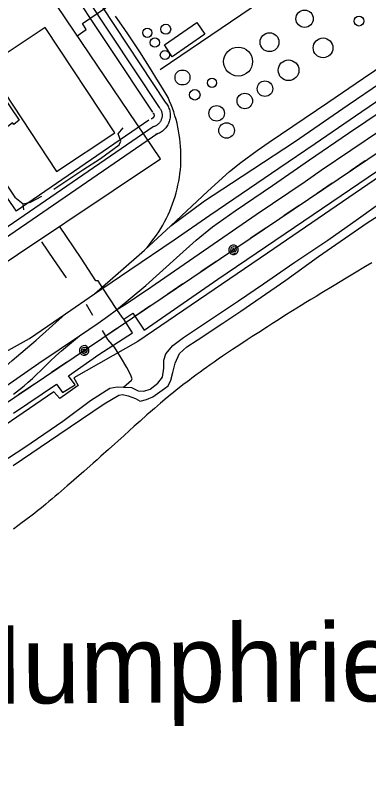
# Model space of a CAD drawing. Extents: x 3355724 to 3393621, y 594744 to 620174.
# Drawn here: x 3387262 to 3387918, y 615262 to 616675 of the extents above; entities that cross this region are included whole.
import ezdxf

# ---------------------------------------------------------------- set-up
doc = ezdxf.new("R2010")
doc.units = 0
for name, color, linetype in [('V-BLDG-OTLN', 7, 'Continuous'), ('V-DOMW-TANK', 7, 'Continuous'), ('V-RAIL-TRAK', 7, 'Continuous'), ('V-ROAD-CNTR', 7, 'Continuous'), ('V-SITE-OTLN', 7, 'Continuous'), ('V-TOPO-GNAM-IDEN', 7, 'Continuous'), ('V-TOPO-SHOR', 7, 'Continuous'), ('V-UTIL-LINE', 7, 'Continuous')]:
    doc.layers.add(name, color=color, linetype=linetype)

msp = doc.modelspace()

# ---------------------------------------------------------------- linework, layer by layer
at = {"layer": 'V-BLDG-OTLN'}
for points in [[(3387553.3, 616598.3), (3387539.4, 616620.3), (3387599.5, 616661.8), (3387614.3, 616640.3)], [(3387201.5, 616455.7), (3387181.3, 616482), (3387221.2, 616512.5), (3387206, 616532.9), (3387166.4, 616504.6), (3387146.8, 616534.8), (3387204.5, 616575.5), (3387269.8, 616480.5), (3387259.4, 616472.8), (3387257.3, 616475.6), (3387245.2, 616466.3), (3387238, 616475.6), (3387230.3, 616469.7), (3387226.4, 616474.8)]]:
    msp.add_lwpolyline(points, close=True, dxfattribs=at)
at = {"layer": 'V-DOMW-TANK'}
for centre, radius in [((3387799.3, 616668.6), 16.1), ((3387900.4, 616664.4), 9.17), ((3387507.4, 616642.7), 8.61), ((3387541.6, 616649.3), 9.17), ((3387734.3, 616625.2), 17.5), ((3387521.3, 616624.5), 8.61), ((3387833.6, 616614.7), 18.3), ((3387540.1, 616601.4), 8.61), ((3387675.9, 616589.2), 26.9), ((3387769.5, 616573.1), 19.2), ((3387572.7, 616559.7), 13.9), ((3387627.4, 616550), 8.61), ((3387725.8, 616538.9), 14.4), ((3387595.5, 616527.6), 9.72), ((3387688.3, 616516.2), 14.4), ((3387636.1, 616493.2), 14.4), ((3387654.5, 616461.4), 14.4)]:
    msp.add_circle(centre, radius, dxfattribs=at)
at = {"layer": 'V-RAIL-TRAK'}
for points in [[(3387450.3, 616128.8), (3387504.5, 616174.1), (3387561.3, 616225), (3387598.2, 616258), (3387628.6, 616282.7), (3387670.2, 616312.5), (3387739.5, 616359.6), (3387808.7, 616406.9), (3387880.9, 616456.4), (3387945.1, 616499.7), (3388007, 616542.8), (3388063.4, 616581.5), (3388145.5, 616636.7), (3388183, 616661.2), (3388215.5, 616683.5), (3388269.3, 616721.9), (3388344.9, 616770.7), (3388401.5, 616812.1), (3388522.9, 616894.6), (3388588.2, 616939.6), (3388655.4, 616984.5), (3388665.4, 616991.1), (3388707.3, 617020.1), (3388735.1, 617038.3)], [(3387409.6, 616158.5), (3387502, 616239.2), (3387550.9, 616284.7), (3387620, 616348.7), (3387659.7, 616385.4), (3387680.7, 616402.3), (3387711.1, 616424.1), (3387733.4, 616439.7), (3387842.2, 616513.1), (3387908.6, 616558.6), (3388032.9, 616642.8), (3388110, 616695.3), (3388185.6, 616747.4), (3388269, 616803.9), (3388382.3, 616883.3), (3388435.3, 616916.9), (3388497.4, 616961.6), (3388542.1, 616990.6)], [(3387550.9, 616284.7), (3387613.8, 616330.9), (3387663.9, 616363.5), (3387703.3, 616389.6), (3387780.4, 616440.5), (3387880.1, 616509.3), (3387939.9, 616550), (3388049, 616625.3), (3388135, 616682.1), (3388190.6, 616721.1), (3388279.8, 616781.3)], [(3387502, 616239.2), (3387506.8, 616244.6), (3387511.5, 616250.1), (3387516, 616255.8), (3387520.3, 616261.6), (3387524.5, 616267.5), (3387528.5, 616273.5), (3387532.4, 616279.7), (3387536.1, 616285.9), (3387539.5, 616292.2), (3387542.9, 616298.7), (3387546, 616305.2), (3387548.9, 616311.8), (3387551.7, 616318.5), (3387554.3, 616325.3), (3387556.7, 616332.1), (3387558.9, 616339), (3387560.8, 616346), (3387562.6, 616353), (3387564.2, 616360), (3387565.6, 616367.1), (3387566.9, 616374.3), (3387567.9, 616381.4), (3387568.7, 616388.6), (3387569.3, 616395.9), (3387569.7, 616403.1), (3387569.9, 616410.3), (3387569.8, 616417.6), (3387569.6, 616424.8), (3387569.2, 616432), (3387568.6, 616439.2), (3387567.8, 616446.4), (3387566.8, 616453.6), (3387565.5, 616460.7), (3387564.1, 616467.8), (3387562.5, 616474.9), (3387560.7, 616481.9), (3387558.7, 616488.8), (3387556.5, 616495.7), (3387554.1, 616502.6), (3387551.5, 616509.3), (3387548.7, 616516), (3387545.8, 616522.6), (3387535.6, 616539.8), (3387525.3, 616556.8), (3387514.8, 616573.8), (3387504.2, 616590.7), (3387493.3, 616607.4), (3387482.3, 616624), (3387471.1, 616640.5), (3387459.8, 616656.9), (3387448.3, 616673.2)], [(3387075.1, 615871.5), (3387104.9, 615900.4), (3387157, 615946.7), (3387160.7, 615950), (3387198.9, 615983.4), (3387256.4, 616034.6), (3387300.9, 616072.7), (3387355.3, 616121.4), (3387409.6, 616158.5), (3387474.7, 616202.7), (3387557, 616258.4), (3387623.7, 616304.1), (3387697.1, 616354.1), (3387751.4, 616391.8), (3387818.8, 616437.5), (3387893.8, 616488.6), (3387981.7, 616548.6)], [(3387603.5, 616232.7), (3387709.7, 616305.3), (3387740, 616325.7), (3387770.1, 616346.3), (3387800.2, 616367), (3387830.1, 616387.9), (3387885.2, 616424.9), (3387940.2, 616462.1)], [(3387258.9, 615972.3), (3387270.4, 615980.8), (3387278.5, 615987.5), (3387286.5, 615994.3), (3387294.3, 616001.4), (3387302, 616008.5), (3387309.6, 616015.9), (3387317, 616023.3), (3387327.3, 616033.3), (3387337.8, 616043.1), (3387348.4, 616052.7), (3387359.2, 616062.1), (3387370.2, 616071.4), (3387381.3, 616080.4), (3387398.8, 616092.2), (3387416.1, 616104.2), (3387433.3, 616116.4), (3387450.3, 616128.8), (3387464.9, 616138), (3387479.3, 616147.4), (3387493.6, 616156.9), (3387507.8, 616166.6), (3387521.9, 616176.5), (3387603.5, 616232.7)], [(3386728.1, 615708.3), (3386943.1, 615855.4), (3387023.4, 615910.8), (3387097.6, 615961.1), (3387192.1, 616023.3), (3387238.8, 616047.7), (3387288.9, 616075.6), (3387355.3, 616121.4)], [(3386995.7, 615816.8), (3387040.5, 615848.3), (3387075.1, 615871.5), (3387125.2, 615905.6), (3387203.1, 615958.9), (3387306.2, 616029.9), (3387381.3, 616080.4)]]:
    msp.add_lwpolyline(points, dxfattribs=at)
at = {"layer": 'V-ROAD-CNTR'}
for points in [[(3386982.9, 617326.4), (3387529.5, 616503.9)], [(3386873.2, 616875.5), (3387264.1, 616311.9)], [(3387272.8, 616863.1), (3387517, 616495.6)], [(3387422.2, 616692.4), (3387542, 616512.2)], [(3387541.1, 616513.4), (3387542.2, 616512), (3387543.6, 616510.2), (3387544.7, 616508.3), (3387545.8, 616506.4), (3387546.8, 616504.4), (3387547.6, 616502.3), (3387548.3, 616500.2), (3387548.9, 616498), (3387549.4, 616495.9), (3387549.7, 616493.7), (3387549.9, 616491.4), (3387549.9, 616489.2), (3387549.8, 616487), (3387549.6, 616484.8), (3387549.3, 616482.6), (3387548.8, 616480.4), (3387548.2, 616478.2), (3387547.4, 616476.1), (3387546.5, 616474.1), (3387545.5, 616472.1), (3387544.4, 616470.2), (3387543.2, 616468.3), (3387541.9, 616466.5), (3387540.4, 616464.8), (3387538.9, 616463.2), (3387537.2, 616461.7), (3387535.5, 616460.3), (3387533.7, 616459), (3387531.8, 616457.8), (3387529.9, 616456.7), (3387527.8, 616455.8), (3387525.8, 616454.9), (3387523.7, 616454.3), (3387522.5, 616453.9)], [(3387529.5, 616503.9), (3387530.4, 616502.9), (3387531.1, 616501.8), (3387531.9, 616500.7), (3387532.5, 616499.5), (3387533.1, 616498.3), (3387533.6, 616497.1), (3387534, 616495.9), (3387534.3, 616494.6), (3387534.6, 616493.3), (3387534.8, 616492), (3387534.9, 616490.7), (3387534.9, 616489.3), (3387534.9, 616488), (3387534.7, 616486.7), (3387534.5, 616485.4), (3387534.2, 616484.1), (3387533.9, 616482.8), (3387533.4, 616481.6), (3387532.9, 616480.4), (3387532.3, 616479.2), (3387531.7, 616478.1), (3387530.9, 616477), (3387530.1, 616475.9), (3387529.3, 616474.9), (3387528.4, 616473.9), (3387527.4, 616473), (3387526.4, 616472.2), (3387525.3, 616471.4), (3387524.2, 616470.7), (3387523, 616470.1), (3387521.8, 616469.5), (3387520.6, 616469), (3387519.3, 616468.6), (3387518.5, 616468.4)], [(3387517.9, 616494.4), (3387518.5, 616493.7), (3387518.7, 616493.4), (3387519, 616493), (3387519.2, 616492.6), (3387519.3, 616492.3), (3387519.5, 616491.9), (3387519.6, 616491.5), (3387519.7, 616491.1), (3387519.8, 616490.7), (3387519.9, 616490.3), (3387519.9, 616489.9), (3387519.9, 616489.5), (3387519.9, 616489.1), (3387519.9, 616488.6), (3387519.8, 616488.2), (3387519.7, 616487.8), (3387519.6, 616487.4), (3387519.4, 616487), (3387519.3, 616486.7), (3387519.1, 616486.3), (3387518.9, 616485.9), (3387518.7, 616485.6), (3387518.4, 616485.3), (3387518.1, 616485), (3387517.9, 616484.7), (3387517.6, 616484.4), (3387517.2, 616484.1), (3387516.9, 616483.9), (3387516.6, 616483.7), (3387516.2, 616483.5), (3387515.8, 616483.3), (3387515.4, 616483.1), (3387515, 616483), (3387514.5, 616482.8)], [(3387518.5, 616468.4), (3386288.7, 615624.2)], [(3387510, 616480.8), (3387264.1, 616311.9)], [(3387527, 616456), (3386297.2, 615611.8)], [(3387923.9, 616215.7), (3387912.3, 616208.8), (3387891.9, 616196.7), (3387876.7, 616187.6), (3387853.9, 616173.8), (3387831.1, 616160), (3387820.6, 616153.6), (3387810.8, 616147.6), (3387801.6, 616142), (3387793, 616136.7), (3387777, 616126.7), (3387762.9, 616117.9), (3387750.7, 616110.2), (3387739.9, 616103.4), (3387730.6, 616097.4), (3387714.2, 616086.9), (3387702, 616079), (3387692.8, 616073), (3387679.1, 616064), (3387665.4, 616055), (3387656, 616048.7), (3387647.1, 616042.7), (3387638.9, 616037.1), (3387631.2, 616031.7), (3387624.1, 616026.7), (3387617.3, 616021.9), (3387611.1, 616017.4), (3387605.2, 616013.2), (3387599.8, 616009.2), (3387594.7, 616005.4), (3387589.9, 616001.8), (3387585.5, 615998.5), (3387581.3, 615995.3), (3387573.5, 615989.3), (3387566.8, 615984.1), (3387560.9, 615979.4), (3387555.8, 615975.3), (3387551.3, 615971.7), (3387547.4, 615968.5), (3387540.6, 615962.9), (3387535.6, 615958.6), (3387531.8, 615955.4), (3387526.1, 615950.6), (3387520.5, 615945.7), (3387513.4, 615939.5), (3387506.7, 615933.6), (3387494.2, 615922.4), (3387483.2, 615912.7), (3387464.2, 615895.6), (3387435.6, 615869.9), (3387421.3, 615857), (3387414.1, 615850.7), (3387406.9, 615844.3), (3387389.4, 615828.8), (3387376.2, 615817.2), (3387366.3, 615808.6), (3387358.9, 615802.1), (3387347.7, 615792.4), (3387342.1, 615787.6), (3387336.4, 615782.8), (3387330.5, 615777.8), (3387324.8, 615773), (3387319.2, 615768.4), (3387313.8, 615764), (3387308.5, 615759.8), (3387303.3, 615755.7), (3387298.3, 615751.7), (3387293.5, 615747.9), (3387288.7, 615744.3), (3387284.1, 615740.8), (3387279.7, 615737.4), (3387275.3, 615734.1), (3387266.9, 615727.8), (3387258.9, 615722)]]:
    msp.add_lwpolyline(points, dxfattribs=at)
msp.add_spline([(3387577.8, 614629.5), (3387581.6, 614641.7), (3387575.8, 614663.1), (3387570.9, 614700.8), (3387596.3, 614736.1), (3387656, 614782.5), (3387725.8, 614834.6), (3387847.5, 614927.9), (3387984.4, 615012.4), (3388117.3, 615092.1), (3388267, 615184.4), (3388360.5, 615256.6), (3388404, 615318.4), (3388387.5, 615376), (3388337.1, 615461.4), (3388243.5, 615603.9), (3388138.9, 615748.2), (3388071.3, 615880.8), (3388025.2, 616016.1), (3387975.5, 616193.5), (3388015.8, 616307.2), (3388088.2, 616351.1), (3388223.5, 616358), (3388298.3, 616404.9), (3388361.5, 616454.7), (3388367.9, 616494.7), (3388340.8, 616541.8), (3388303.3, 616605.5), (3388232.8, 616628.8), (3388182.1, 616633.4), (3388133, 616694.7), (3388031.4, 616827.3), (3387946.9, 616946.1), (3387893.3, 617037), (3387855.7, 617021), (3387760.1, 616964.4), (3387615, 616852.4)], degree=3, dxfattribs=at)
at = {"layer": 'V-SITE-OTLN'}
for p, q in [((3388031.3, 616439.5), (3387730.4, 616234)), ((3387730.4, 616234), (3387489.9, 616069.8)), ((3387489.9, 616069.8), (3387371.3, 616002.3)), ((3387371.3, 616002.3), (3387379, 615988.2)), ((3387379, 615988.2), (3387344.7, 615964.5)), ((3387334.1, 615976.4), (3387231.3, 615906.9)), ((3387344.7, 615964.5), (3387334.1, 615976.4))]:
    msp.add_line(p, q, dxfattribs=at)
msp.add_lwpolyline([(3387338.7, 616385.5), (3387446.8, 616457.1), (3387317.6, 616652.3), (3387209.5, 616580.7)], close=True, dxfattribs=at)
at = {"layer": 'V-TOPO-SHOR'}
for p, q in [((3387278.4, 616314.4), (3387277, 616325.2)), ((3387406.5, 616118.1), (3387394.2, 616138.6))]:
    msp.add_line(p, q, dxfattribs=at)
for points in [[(3387333.7, 616352.5), (3387387.4, 616388.4), (3387420.2, 616409.4), (3387455.1, 616435), (3387458.4, 616441.4), (3387453.4, 616454.9), (3387462.3, 616466.2)], [(3387185.5, 616444.2), (3387225.2, 616391.4), (3387261.5, 616337.4), (3387277, 616325.2), (3387290.5, 616328.3), (3387311.7, 616339.5)], [(3387232.9, 615843.8), (3387280.3, 615874), (3387350.3, 615922.1), (3387402, 615960.3), (3387438.1, 615983.2), (3387451.2, 615986), (3387463.2, 615985.5), (3387478.3, 615984.8), (3387490.4, 615978.6), (3387501.2, 615977.6), (3387512.8, 615981.5), (3387527, 615992.9), (3387535.8, 616003.9), (3387538.3, 616020.4), (3387538.1, 616035.1), (3387541.7, 616047.1), (3387554.7, 616062.3), (3387574.8, 616077.2), (3387621, 616108.1), (3387676.4, 616145.5), (3387723, 616177.2), (3387779.2, 616215.8), (3387842.5, 616258.2), (3387899.5, 616297.9), (3387956.4, 616338.7)], [(3387258.5, 615840), (3387343, 615897.6), (3387427.2, 615954.6), (3387454.4, 615970.3), (3387461.5, 615971.5), (3387472.1, 615969.4), (3387485.3, 615964.2), (3387494.3, 615959.5), (3387505.6, 615962.2), (3387517.9, 615967.3), (3387539.5, 615982.5), (3387545.8, 615987.5), (3387551.3, 615998.4), (3387554.9, 616012.4), (3387558.8, 616029.7), (3387566.9, 616047.4), (3387580.6, 616060.3), (3387600, 616072.6), (3387647.3, 616103.9), (3387681.2, 616126.4), (3387764.2, 616183.7), (3387824.9, 616227.6), (3387915.7, 616290.2), (3387951.5, 616313.2)], [(3387357.6, 616188), (3387333.6, 616221.9), (3387311.8, 616255.1)], [(3387463.2, 615985.5), (3387478.1, 615998.4), (3387479.2, 616000.7), (3387476.1, 616008.9), (3387469.2, 616021.9), (3387457.7, 616041.7), (3387446.2, 616059.6), (3387434.4, 616073.7), (3387424.1, 616090.1)]]:
    msp.add_lwpolyline(points, dxfattribs=at)
at = {"layer": 'V-UTIL-LINE'}
for points in [[(3390862.5, 618393.4), (3386415.7, 615396.7), (3387373.6, 614856.8), (3390174.5, 613140.8)], [(3386600.5, 615781.2), (3386864.1, 615961.5), (3387178.2, 616172.7), (3387531.6, 616408.8), (3387356.1, 616668.5), (3387231, 616853.4), (3387058, 617121), (3386879.8, 617376.6), (3386723.8, 617604.2), (3386569.8, 617836.3), (3386395.6, 618090), (3386274.8, 618262.8)], [(3387377.4, 616636.9), (3387394.1, 616648.6), (3387387.1, 616659.8), (3387561.8, 616779.5), (3387660.5, 616846.1), (3387793.6, 616937.8), (3387931.3, 617030.3), (3388035.2, 617099.6), (3388038.6, 617092.7), (3388111.9, 616985.9), (3388161.3, 616913.7), (3388117.4, 616884.1), (3388141.6, 616849.8)], [(3387531, 616574.4), (3387775.3, 616740.2), (3387790.9, 616749.4)], [(3387463.8, 616111.1), (3387480.2, 616122.2), (3387501.6, 616090.9), (3387638.2, 616185.3), (3387797.6, 616294.1), (3387969.2, 616409.8)], [(3387911.9, 616404.9), (3387883.7, 616385.9)], [(3387850.6, 616363.6), (3387822.4, 616344.6)], [(3387789.2, 616322.2), (3387761, 616303.2)], [(3387259, 615936.8), (3387338.7, 615991.1), (3387349.8, 615975.1), (3387373.6, 615989.6), (3387361.1, 616006), (3387417.3, 616045.7), (3387479.8, 616086.2), (3387463.8, 616111.1), (3387460.4, 616115.2), (3387451, 616129.2), (3387423.7, 616170.8), (3387416, 616182.6), (3387411.9, 616182.6), (3387384.4, 616224.7), (3387344.6, 616283.8)], [(3387727.8, 616280.9), (3387699.6, 616261.9)], [(3387667.3, 616240.1), (3387670, 616239), (3387669.4, 616241.3), (3387666.8, 616242.2), (3387664.6, 616240.3), (3387666.4, 616237.4), (3387670.9, 616236.4), (3387673.2, 616240.1), (3387671.6, 616244.7), (3387667.2, 616245.8), (3387663, 616244.1), (3387661.6, 616239.5), (3387664.4, 616234.8), (3387672.3, 616232.6), (3387674.8, 616235.1), (3387676.1, 616238.4), (3387676.1, 616241.9), (3387674.7, 616245.1), (3387672.3, 616247.6), (3387669, 616248.9), (3387665.5, 616248.9), (3387662.3, 616247.5), (3387659.8, 616245.1), (3387658.5, 616241.8), (3387658.5, 616238.3), (3387659.8, 616235), (3387662.3, 616232.6), (3387665.6, 616231.2), (3387669.1, 616231.3), (3387672.3, 616232.6)], [(3387635, 616218.3), (3387606.8, 616199.3)], [(3387573.6, 616176.9), (3387545.4, 616157.9)], [(3387512.2, 616135.6), (3387484, 616116.6)], [(3387450.9, 616094.2), (3387422.7, 616075.2)], [(3387390.3, 616053.4), (3387393, 616052.4), (3387392.4, 616054.6), (3387389.9, 616055.6), (3387387.6, 616053.7), (3387389.4, 616050.8), (3387394, 616049.8), (3387396.2, 616053.4), (3387394.6, 616058), (3387390.2, 616059.1), (3387386, 616057.5), (3387384.7, 616052.9), (3387387.5, 616048.1), (3387395.3, 616046), (3387397.8, 616048.5), (3387399.1, 616051.7), (3387399.1, 616055.2), (3387397.8, 616058.5), (3387395.3, 616060.9), (3387392, 616062.3), (3387388.5, 616062.2), (3387385.3, 616060.9), (3387382.8, 616058.4), (3387381.5, 616055.1), (3387381.5, 616051.6), (3387382.8, 616048.4), (3387385.3, 616045.9), (3387388.6, 616044.6), (3387392.1, 616044.6), (3387395.3, 616046)], [(3387358, 616031.6), (3387329.8, 616012.6)], [(3387296.6, 615990.3), (3387268.4, 615971.3)]]:
    msp.add_lwpolyline(points, dxfattribs=at)

# ---------------------------------------------------------------- texts
at = {"layer": 'V-TOPO-GNAM-IDEN'}
msp.add_text('Humphries', height=145, rotation=0.3574, dxfattribs=at).set_placement((3387135.2, 615397.5))

doc.saveas('drawing.dxf')
